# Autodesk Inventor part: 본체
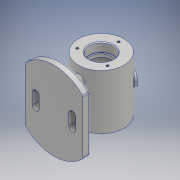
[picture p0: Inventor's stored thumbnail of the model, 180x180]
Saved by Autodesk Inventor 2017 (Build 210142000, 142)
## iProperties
Part Number: 본체
Material: 알루미늄 6061
Document SubType Name: Modeling
Designer: 601-19
Density: 2.7 g/cm^3
Appearance: 알루미늄 - 평지
Mass: 496.239 g
Surface Area: 492.781 cm^2
Volume: 183.792 cm^3
Author: 601-19
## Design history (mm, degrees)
sketch "스케치1"
  geometry: L1 (38, 35.496)-(38, -35.496); L2 (-38, -35.496)-(-38, 35.496); A1 r 52 centre (0, 0) between (38, 35.496) and (-38, 35.496); A2 r 52 centre (0, 0) between (-38, -35.496) and (38, -35.496); A3 r 52 centre (0, 0) between (52, 0) and (-52, 0); 4 further points
  constraints: 6 point on circle, 4 end point, 3 centre point, 2 coincident, 2 horizontal alignment, 2 midpoint, 1 concentric, 1 parallel, 1 vertical alignment
  dimensions: "d2" = 52 radius of A1; "d3" = 52 radius of A2; "d4" = 76 distance between parallel lines of L2 L1; "d5" = 70.99296 distance of L1.start L1.end
extrude "돌출1" new body sketch "스케치1" distance "d6" = 10; taper "d7" = 0 deg
sketch "스케치2"
  geometry: L1 (78, 36)-(92, 36); L2 (92, 36)-(92, -36); L3 (62, 20)-(87, 20); L4 (87, -20)-(62, -20); L5 (62, 24)-(76, 24); L6 (76, 24)-(76, 20); L7 (76, 20)-(62, 20); L8 (78, 36)-(78, 24); L9 (62, -20)-(74.5, -20); L10 (74.5, -20)-(74.5, -24); L11 (74.5, -24)-(62, -24); L12 (78, -36)-(78, -24); L13 (62, 36)-(62, -52.194); L14 (0, -35.496)-(0, -52) reference; L15 (87, 20)-(87, -20); L16 (78, 24)-(62, 24); L17 (78, -24)-(62, -24); L18 (92, -36)-(78, -36); L19 (10, 35.496)-(10, -35.496) reference; 5 further points
  constraints: 34 end point, 6 vertical alignment, 5 horizontal, 4 point on line, 3 midpoint, 3 parallel, 3 perpendicular, 2 horizontal alignment, 1 vertical
  dimensions: "d19" = 62 distance from line of L14 L13.end; "d20" = 72 distance of L1.end L2.end; "d21" = 40 distance of L3.end L4.start; "d22" = 32 diameter of L12.start L13; "d23" = 25 diameter of L10 L13; "d24" = 60 diameter of L2 L13; "d25" = 12 distance of L12.start L12.end; "d26" = 12 distance of L1.start L8.end
revolve "회전1" sketch "스케치2" stored, may be unused: angle "d27" = 90 deg
fillet "모깎기1" dims "d28" = 3
chamfer "모따기1" distance "d29" = 1; stored, may be unused: second distance "d30" = 2, angle "d31" = 45 deg
sketch "스케치3"
  geometry: L1 (-7, -19)-(-7, 19); L2 (7, 19)-(7, -19); L3 (7, -19)-(-7, 19); L4 (-7, -19)-(7, 19); L5 (-28.5, -7.5)-(-28.5, 7.5); L6 (-19.5, 7.5)-(-19.5, -7.5); L7 (-21.882, -3.529)-(-28.5, 7.5); L8 (-28.5, -7.5)-(-19.5, 7.5); L9 (19.5, -7.5)-(19.5, 7.5); L10 (28.5, 7.5)-(28.5, -7.5); L11 (28.5, -7.5)-(19.5, 7.5); L12 (19.5, -7.5)-(28.5, 7.5); A1 r 7 centre (0, 19) between (7, 19) and (-7, 19); A2 r 7 centre (0, -19) between (-7, -19) and (7, -19); A3 r 4.5 centre (24, 7.5) between (28.5, 7.5) and (19.5, 7.5); A4 r 4.5 centre (24, -7.5) between (19.5, -7.5) and (28.5, -7.5); A5 r 4.5 centre (-24, 7.5) between (-19.5, 7.5) and (-28.5, 7.5); A6 r 4.5 centre (-24, -7.5) between (-28.5, -7.5) and (-19.5, -7.5); 11 further points
  constraints: 24 end point, 12 midpoint, 12 point on circle, 6 centre point, 5 horizontal alignment, 3 parallel, 2 point on line
  dimensions: "d32" = 14 distance of L1.end L2.start; "d34" = 9 distance of L5.end L6.start; "d35" = 14 distance of L2.end L1.start; "d36" = 7 radius of A2; "d37" = 38 distance of L1.start L1.end; "d39" = 24 distance of point (0, 0) point (-24, 0); "d40" = 24 distance of point (24, 0) point (0, 0); "d41" = 9 distance of L10.start L9.end; "d42" = 15 distance of L5.end L5.start; "d43" = 15 distance of L9.start L9.end
extrude "돌출2" cut sketch "스케치3" distance "d44" = 10; taper "d45" = 0 deg
extrude "돌출3" join sketch "스케치3" distance "d46" = 27; taper "d47" = 0 deg
sketch "스케치4"
  geometry: L1 (12.935, 84.404)-(19.863, 80.404); L2 (23.428, 86.579)-(16.5, 90.579); L3 (19.863, 80.404)-(23.428, 86.579); L4 (12.935, 84.404)-(16.5, 90.579); C1 r 12.5 at (0, 62) reference; 1 further point
  constraints: 8 end point, 1 parallel, 1 perpendicular
revolve "회전2" sketch "스케치4" stored, may be unused: angle "d54" = 90 deg
sketch "스케치5"
  geometry: C1 r 8 at (0, 0) reference; 1 further point
hole "구멍1" sketch "스케치5" at (0, 0) diameter "d55" = 8; stored, may be unused: countersink angle "d59" = 90 deg, drill point angle "d61" = 118 deg; dims "d56" = 6, "d57" = 4, "d58" = 2, "d60" = 12.5
fillet "모깎기2" dims "d62" = 1
fillet "모깎기3" dims "d66" = 3
fillet "모깎기4" dims "d67" = 3
fillet "모깎기5" dims "d68" = 0.3
fillet "모깎기6" dims "d69" = 1
sketch "스케치6" dims "d70" = 46
  geometry: C1 r 14 at (0, 0) reference; 5 further points
  constraints: 1 coincident, 1 vertical alignment, 6 other
  dimensions: "d73" = 360 deg dimension on point (0, 0) point (0, 23) (derived)
hole "구멍2" sketch "스케치6" at (0, 23), (-19.919, -11.5), (19.919, -11.5) diameter "d75" = 3.242; stored, may be unused: countersink angle "d79" = 90 deg, drill point angle "d81" = 118 deg; dims "d76" = 8, "d77" = 4, "d78" = 2, "d80" = 10
sketch "스케치7"
  geometry: C1 r 42.5 at (0, 0); 1 further point
  constraints: 1 centre point, 1 coincident, 1 other
  dimensions: "d82" = 85 diameter of C1
extrude "돌출4" join sketch "스케치7" distance "d83" = 0.5; taper "d84" = 0 deg
node "솔리드1"
mirror "미러1"
other parameters: "d0" = 104, "d50" = 30 deg, "d51" = 90 deg, "d52" = 33, "d53" = 8
